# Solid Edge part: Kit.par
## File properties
Last saved by: ahadarics
Revision: 77
Dokumentum tartalom típus: 0
Sűrűség: 0,000 kg/m^3
Pontosság: 0,990
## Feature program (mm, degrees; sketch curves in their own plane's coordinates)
base feature "unnamed BaseFeature 1"
thread "unnamed Thread 1"
sketch for "Furat_1" plane through (0, -73.3, 32.5) normal (0, 0, 1) x-axis (0, 1, 0)
  hole centre (1.05, 0) bore radius 7.475
hole "Furat_1" nominal diameter 16.662 finite  ThreadDepth = 13 mm
sketch for "Furat_2" plane through (33, -72.25, 0) normal (1, 0, 0) x-axis (0, 1, 0)
  hole centre (0, 0) bore radius 6.188
hole "Furat_2" nominal diameter 14 finite  ThreadDepth = 17 mm
sketch for "Furat_3" plane through (-33, -72.25, 0) normal (-1, 0, 0) x-axis (0, -1, 0)
  hole centre (0, 0) bore radius 6.188
hole "Furat_3" nominal diameter 14 finite  ThreadDepth = 17 mm
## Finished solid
Body 1: solid body, 72 faces, 76 edges, 6 vertices, 2 internal voids.
  Faces by surface: plane 26, cylinder 24, cone 17, torus 5
  Edges by curve: circle 67, line 6, intersection 3
Bounding box of the edges (mm; curved faces can reach further): 70.000 x 64.000 x 67.750, from (-35, -123.25, -35) to (35, -59.25, 32.75).
Cylindrical faces by radius (mm): R6.185 x2, R6.188 x2, R7.47 x1, R7.475 x1, R8 x2, R10 x1, R10.4 x1, R10.4236 x1, R11.5 x2, R12 x2, R15 x3, R21.5 x2, R22.5 x2, R32.75 x1, R35 x1
Conical faces (half-angle, radius in mm at the cone's reference point): 1.6538 deg R11.75 x1, 3.5477 deg R12.7454 x1, 5.762 deg R10.4 x1, 11.1239 deg R10.0056 x1, 15.3654 deg R10.7214 x1, 19.3654 deg R11.1921 x1, 25.0169 deg R14.31 x1, 30 deg R11.8557 x2, 30 deg R12.2887 x1, 30 deg R15.4263 x1, 30 deg R15.5774 x1, 36.3268 deg R15 x1, 45 deg R7.47 x1, 45 deg R10.15 x2, 45 deg R21.15 x1
Toroidal faces (ring radius, tube radius in mm): R10.3 r0.3 x1, R10.3085 r0.3 x1, R11.4279 r0.25 x1, R12.2464 r0.5 x1, R14.8 r0.2 x1
Planar faces by outward normal: +x 3, +y 7, +z 2, -x 3, -y 11
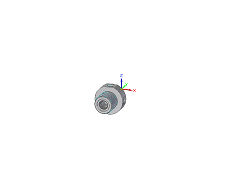
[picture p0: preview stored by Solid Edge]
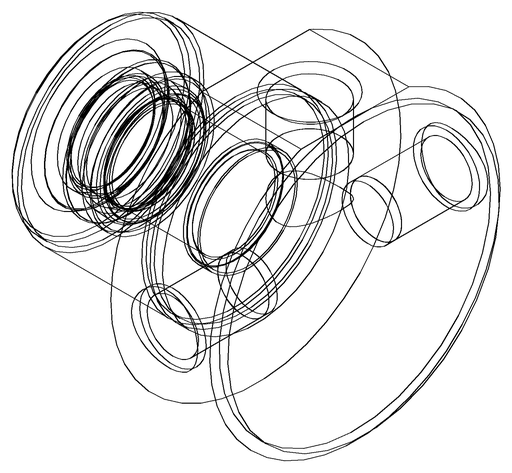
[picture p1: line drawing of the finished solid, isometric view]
